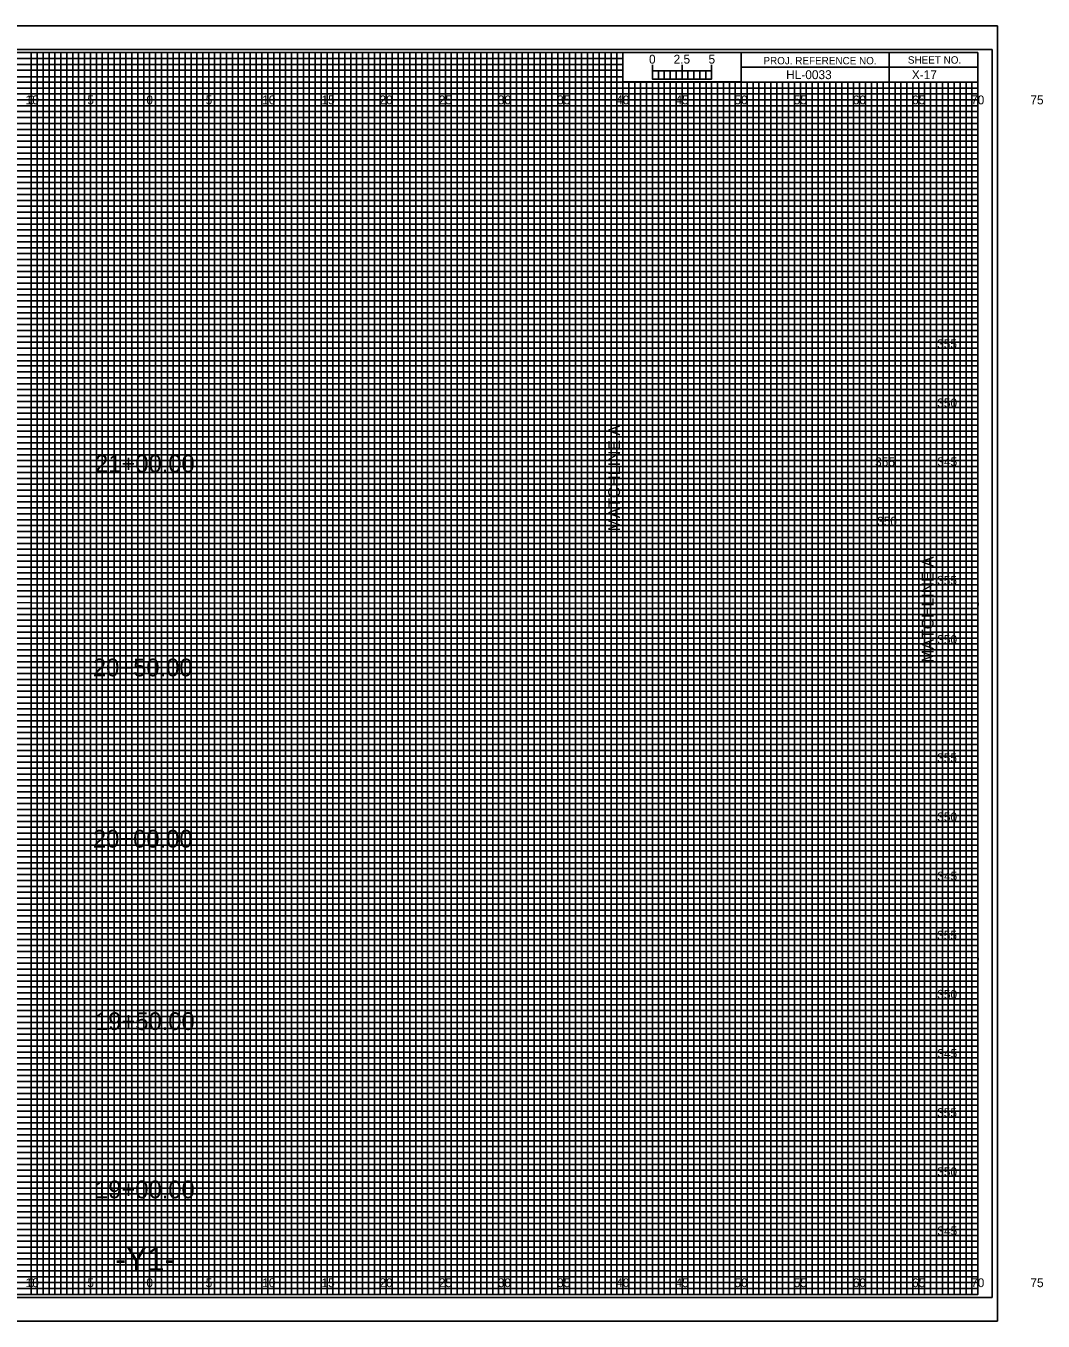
# Model space of a CAD drawing. Extents: x -7 to 166, y 218 to 327.
# Drawn here: x 79.5 to 165.5, y 217.7 to 327.2 of the extents above; entities that cross this region are included whole.
import ezdxf

# ---------------------------------------------------------------- set-up
doc = ezdxf.new("R2010")
doc.units = 0
for name, color, linetype in [('Prop XS Alignment Label', 7, 'Continuous'), ('Prop XS Bar Scale Labels', 7, 'Continuous'), ('Prop XS Elevation Labels', 7, 'Continuous'), ('Prop XS Hydro Elevations', 7, 'Continuous'), ('Prop XS Offset Labels', 7, 'Continuous'), ('Prop XS Project Number', 7, 'Continuous'), ('Prop XS Sheet Number', 7, 'Continuous'), ('Prop XS Station Labels', 7, 'Continuous'), ('Scratch_Level_0', 7, 'Continuous'), ('Sheet Cross Section CELL', 7, 'Continuous'), ('Sheet Cross Section Grid Major CELL', 7, 'Continuous'), ('Sheet Cross Section Grid Middle CELL', 7, 'Continuous'), ('Sheet Cross Section Grid Minor 1 CELL', 7, 'Continuous'), ('Sheet Cross Section Grid Minor 2 CELL', 7, 'Continuous'), ('Sheet Cross Section Scale CELL', 7, 'Continuous'), ('Sheet Cutting Line CELL', 7, 'Continuous'), ('Sheet DOT Grid CELL', 7, 'Continuous'), ('Sheet Plot Border Inside CELL', 7, 'Continuous'), ('Sheet Plot Border Outside CELL', 7, 'Continuous')]:
    doc.layers.add(name, color=color, linetype=linetype)

msp = doc.modelspace()

# ---------------------------------------------------------------- linework, layer by layer
at = {"layer": 'Prop XS Offset Labels'}
for p, q in [((130, 293.5), (130, 284)), ((155, 282.5), (155, 271.5))]:
    msp.add_line(p, q, dxfattribs=at)
msp.add_lwpolyline([(128, 294.5), (154.5, 294.5), (154.5, 283.5), (128, 283.5)], close=True, dxfattribs=at)
at = {"layer": 'Scratch_Level_0'}
msp.add_lwpolyline([(130, 293.5), (150, 293.5), (150, 284), (130, 284)], close=True, dxfattribs=at)
at = {"layer": 'Sheet Cross Section CELL'}
for p, q in [((152.5, 325), (152.5, 322.5)), ((152.5, 322.5), (152.5, 325)), ((160, 323.75), (140, 323.75)), ((140, 323.75), (140, 322.5)), ((140, 322.5), (160, 322.5))]:
    msp.add_line(p, q, dxfattribs=at)
for points in [[(160, 325), (0, 325), (0, 220), (160, 220)], [(140, 325), (130, 325), (130, 322.51), (140, 322.51)], [(160, 325), (140, 325), (140, 322.5), (160, 322.5)]]:
    msp.add_lwpolyline(points, close=True, dxfattribs=at)
at = {"layer": 'Sheet Cross Section Grid Major CELL'}
for p, q in [((85, 325), (80, 325)), ((80, 325), (80, 220)), ((85, 220), (85, 325)), ((95, 325), (90, 325)), ((90, 325), (90, 220)), ((95, 220), (95, 325)), ((105, 325), (100, 325)), ((100, 325), (100, 220)), ((105, 220), (105, 325)), ((115, 325), (110, 325)), ((110, 325), (110, 220)), ((115, 220), (115, 325)), ((125, 325), (120, 325)), ((120, 325), (120, 220)), ((125, 220), (125, 325)), ((130, 325), (130, 220)), ((135, 220), (135, 322.5)), ((145, 322.5), (140, 322.5)), ((140, 322.5), (140, 220)), ((145, 220), (145, 322.5)), ((155, 322.5), (150, 322.5)), ((150, 322.5), (150, 220)), ((155, 220), (155, 322.5)), ((80, 220), (75, 220)), ((90, 220), (85, 220)), ((100, 220), (95, 220)), ((110, 220), (105, 220)), ((120, 220), (115, 220)), ((130, 220), (125, 220)), ((140, 220), (135, 220)), ((150, 220), (145, 220)), ((160, 220), (155, 220)), ((160, 220), (160, 220))]:
    msp.add_line(p, q, dxfattribs=at)
for points in [[(0, 320), (160, 320), (160, 315), (0, 315)], [(0, 310), (160, 310), (160, 305), (0, 305)], [(0, 300), (160, 300), (160, 295), (0, 295)], [(0, 290), (160, 290), (160, 285), (0, 285)], [(0, 280), (160, 280), (160, 275), (0, 275)], [(0, 270), (160, 270), (160, 265), (0, 265)], [(0, 260), (160, 260), (160, 255), (0, 255)], [(0, 250), (160, 250), (160, 245), (0, 245)], [(0, 240), (160, 240), (160, 235), (0, 235)], [(0, 230), (160, 230), (160, 225), (0, 225)]]:
    msp.add_lwpolyline(points, dxfattribs=at)
at = {"layer": 'Sheet Cross Section Grid Middle CELL'}
for points in [[(77.5, 325), (82.5, 325), (82.5, 220), (87.5, 220), (87.5, 325), (92.5, 325), (92.5, 220), (97.5, 220), (97.5, 325), (102.5, 325), (102.5, 220), (107.5, 220), (107.5, 325), (112.5, 325), (112.5, 220), (117.5, 220), (117.5, 325), (122.5, 325), (122.5, 220), (127.5, 220), (127.5, 325), (129.97, 325), (130, 325), (130, 322.5), (132.5, 322.5), (132.5, 220), (137.5, 220), (137.5, 322.5), (142.5, 322.5), (142.5, 220), (147.5, 220), (147.5, 322.5), (152.5, 322.5), (152.5, 220), (157.5, 220), (157.5, 322.5)], [(0, 322.5), (137.5, 322.5)], [(0, 312.5), (160, 312.5), (160, 317.5), (0, 317.5)], [(0, 302.5), (160, 302.5), (160, 307.5), (0, 307.5)], [(0, 292.5), (160, 292.5), (160, 297.5), (0, 297.5)], [(0, 282.5), (160, 282.5), (160, 287.5), (0, 287.5)], [(0, 272.5), (160, 272.5), (160, 277.5), (0, 277.5)], [(0, 262.5), (160, 262.5), (160, 267.5), (0, 267.5)], [(0, 252.5), (160, 252.5), (160, 257.5), (0, 257.5)], [(0, 242.5), (160, 242.5), (160, 247.5), (0, 247.5)], [(0, 232.5), (160, 232.5), (160, 237.5), (0, 237.5)], [(0, 222.5), (160, 222.5), (160, 227.5), (0, 227.5)]]:
    msp.add_lwpolyline(points, dxfattribs=at)
at = {"layer": 'Sheet Cross Section Grid Minor 1 CELL'}
for p, q in [((0, 324.5), (130, 324.5)), ((130, 324.5), (130, 323.99)), ((130, 323.99), (0, 323.99)), ((0, 323.5), (130, 323.5)), ((130, 323.5), (130, 322.94)), ((130, 322.94), (0, 322.94)), ((0, 322), (160, 322))]:
    msp.add_line(p, q, dxfattribs=at)
for points in [[(0, 321.5), (135, 321.5), (160, 321.5), (160, 321), (0, 321)], [(0, 320.5), (160, 320.5), (160, 319.5), (0, 319.5)], [(0, 319), (160, 319), (160, 318.5), (0, 318.49)], [(0, 318), (160, 318), (160, 317), (0, 317)], [(0, 316.5), (160, 316.5), (160, 316), (0, 316)], [(0, 315.5), (160, 315.5), (160, 314.5), (0, 314.5)], [(0, 314), (160, 314), (160, 313.5), (0, 313.5)], [(0, 313), (160, 313), (160, 312), (0, 312)], [(0, 311.5), (160, 311.5), (160, 311), (0, 311)], [(0, 310.5), (160, 310.5), (160, 309.5), (0, 309.5)], [(0, 309), (160, 309), (160, 308.5), (0, 308.5)], [(0, 308), (160, 308), (160, 306.98), (160, 306.5), (160, 306), (0, 306)], [(0, 307), (160, 307), (160, 306.5), (0, 306.5)], [(0, 305.5), (160, 305.5), (160, 304.5), (0, 304.51)], [(0, 304.51), (160, 304.5), (160, 304), (0, 304)], [(0, 303.5), (160, 303.5), (160, 303), (0, 303)], [(0, 302), (160, 302), (160, 301.5), (0, 301.5)], [(0, 301), (160, 301), (160, 300.5), (0, 300.5)], [(-0.04, 299.44), (160, 299.44), (160, 298.94), (-0.04, 298.94)], [(0, 298.5), (160, 298.5), (160, 298), (0, 298)], [(0, 297), (160, 297), (160, 296.5), (0, 296.5)], [(0, 296), (160, 296), (160, 295.5), (0, 295.5)], [(0, 294.5), (160, 294.5), (160, 294), (0, 294)], [(0, 293.5), (160, 293.5), (160, 293), (0, 293)], [(0, 292), (160, 292), (160, 291.5), (0, 291.5)], [(0, 291), (160, 291), (160, 290.5), (0, 290.5)], [(0, 289.5), (160, 289.5), (160, 288.99), (0, 289)], [(0, 288.5), (160, 288.5), (160, 288), (0, 288)], [(0, 287), (160, 287), (160, 286.5), (0, 286.5)], [(0, 286), (160, 286), (160, 285.5), (0, 285.5)], [(0, 284.5), (160, 284.5), (160, 284), (0, 284)], [(0, 283.5), (160, 283.5), (160, 283), (0, 283)], [(0, 282), (160, 282), (160, 281.5), (0, 281.5)], [(0, 281), (160, 281), (160, 280.5), (0, 280.5)], [(0, 279.5), (160, 279.5), (160, 279), (0, 279)], [(0, 278.5), (160.03, 278.45), (160, 278), (0, 278)], [(0, 277), (160, 277), (160, 276.5), (0, 276.5)], [(0, 276), (160, 276), (160, 275.5), (0, 275.5)], [(0, 274.5), (160, 274.5), (160, 274), (0, 274)], [(0, 273.5), (160, 273.5), (160, 273), (0, 273)], [(0, 272), (160, 272), (160, 271.5), (0, 271.5)], [(0, 271), (160, 271), (160, 270.5), (0, 270.5)], [(0, 269.5), (160, 269.5), (160, 269), (0, 269)], [(0, 268.5), (160, 268.5), (160, 268), (0, 268)], [(0, 267), (160, 267), (160, 266.5), (0, 266.5)], [(0, 266), (160, 266), (160, 265.5), (0, 265.5)], [(0, 264.5), (160, 264.5), (160, 264), (0, 264)], [(0, 263.5), (160, 263.5), (160, 263), (0, 263)], [(0, 262), (160, 262), (160, 261.5), (0, 261.5)], [(0, 261), (160, 261), (160, 260.5), (0, 260.5)], [(0, 259.5), (160, 259.5), (160, 258.99), (0, 259)], [(0, 258.5), (160, 258.5), (160, 258), (0, 258)], [(0, 257), (160, 257), (160, 256.5), (0, 256.5)], [(0, 256), (160, 256), (160, 255.5), (0, 255.5)], [(0, 254.5), (160, 254.5), (160, 254), (0, 254)], [(0, 253.5), (160, 253.5), (160, 253), (0, 253)], [(0, 252), (160, 252), (160, 251.5), (0, 251.5)], [(0, 251), (160, 251), (160, 250.5), (0, 250.5)], [(0, 249.5), (160, 249.5), (160, 249), (0, 249)], [(0, 248.5), (160.03, 248.46), (160, 248), (0, 248)], [(0, 247), (160, 247), (160, 246.5), (0, 246.5)], [(0, 246), (160, 246), (160, 245.5), (0, 245.5)], [(0, 244.5), (160, 244.5), (160, 244), (0, 244)], [(0, 243.5), (160, 243.5), (160, 243), (0, 243)], [(0, 242), (160, 242), (160, 241.5), (0, 241.5)], [(0, 241), (160, 241), (160, 240.5), (0, 240.5)], [(0, 239.5), (160, 239.5), (160, 239), (0, 239)], [(0, 238.5), (160, 238.5), (160, 238), (0, 238)], [(0, 237), (160, 237), (160, 236.5), (0, 236.5)], [(0, 236), (160, 236), (160, 235.5), (0, 235.5)], [(0, 234.5), (160, 234.5), (160, 234), (0, 234)], [(0, 233.5), (160, 233.5), (160, 233), (0, 233)], [(0, 232), (160, 232), (160, 231.5), (0, 231.5)], [(0, 231), (160, 231), (160, 230.5), (0, 230.5)], [(0, 229.5), (160, 229.5), (160, 229), (0, 229)], [(0, 228.5), (160, 228.5), (160, 228), (0, 228)], [(0, 227), (160, 227), (160, 226.5), (0, 226.5)], [(0, 226), (160, 226), (160, 225.5), (0, 225.5)], [(0, 224.5), (160, 224.5), (160, 224), (0, 224)], [(0, 223.5), (160, 223.5), (160, 223), (0, 223)], [(0, 222), (160, 222), (160, 221.5), (0, 221.5)], [(0, 221), (160, 221), (160, 220.5), (0, 220.5)]]:
    msp.add_lwpolyline(points, dxfattribs=at)
at = {"layer": 'Sheet Cross Section Grid Minor 2 CELL'}
for p, q in [((133.5, 322.5), (133, 322.5)), ((133, 322.5), (133, 220)), ((133.5, 220), (133.5, 322.5)), ((134.5, 322.5), (134, 322.5)), ((134, 322.5), (134, 220)), ((134.5, 220), (134.5, 322.5)), ((133, 220), (132.5, 220)), ((134, 220), (133.5, 220))]:
    msp.add_line(p, q, dxfattribs=at)
for points in [[(80, 220), (80.5, 220), (80.5, 325), (81, 325), (81, 220)], [(81, 220), (81.5, 220), (81.5, 325), (82, 325), (82, 220)], [(82.5, 220), (83, 220), (83, 325), (83.5, 325), (83.5, 220)], [(83.5, 220), (84, 220), (84, 325), (84.5, 325), (84.5, 220)], [(85, 220), (85.5, 220), (85.5, 325), (86, 325), (86, 220)], [(86, 220), (86.5, 220), (86.5, 325), (87, 325), (87, 220)], [(87.5, 220), (88, 220), (88, 325), (88.5, 325), (88.5, 220)], [(88.5, 220), (89, 220), (89, 325), (89.5, 325), (89.5, 220)], [(90, 220), (90.5, 220), (90.5, 325), (91, 325), (91, 220)], [(91, 220), (91.5, 220), (91.5, 325), (92, 325), (92, 220)], [(92.5, 220), (93, 220), (93, 325), (93.5, 325), (93.5, 220)], [(93.5, 220), (94, 220), (94, 325), (94.5, 325), (94.5, 220)], [(95, 220), (95.5, 220), (95.5, 325), (96, 325), (96, 220)], [(96, 220), (96.5, 220), (96.5, 325), (97, 325), (97, 220)], [(97.5, 220), (98, 220), (98, 325), (98.5, 325), (98.5, 220)], [(98.5, 220), (99, 220), (99, 325), (99.5, 325), (99.5, 220)], [(100, 220), (100.5, 220), (100.5, 325), (101, 325), (101, 220)], [(101, 220), (101.5, 220), (101.5, 325), (102, 325), (102, 220)], [(102.5, 220), (103, 220), (103, 325), (103.5, 325), (103.5, 220)], [(103.5, 220), (104, 220), (104, 325), (104.5, 325), (104.5, 220)], [(105, 220), (105.5, 220), (105.5, 325), (106, 325), (106, 220)], [(106, 220), (106.5, 220), (106.5, 325), (107, 325), (107, 220)], [(107.5, 220), (108, 220), (108, 325), (108.5, 325), (108.5, 220)], [(108.5, 220), (109, 220), (109, 325), (109.5, 325), (109.5, 220)], [(110, 220), (110.5, 220), (110.5, 325), (111, 325), (111, 220)], [(111, 220), (111.5, 220), (111.5, 325), (112, 325), (112, 220)], [(112.5, 220), (113, 220), (113, 325), (113.5, 325), (113.5, 220)], [(113.5, 220), (114, 220), (114, 325), (114.5, 325), (114.5, 220)], [(115, 220), (115.5, 220), (115.5, 325), (116, 325), (116, 220)], [(116, 220), (116.5, 220), (116.5, 325), (117, 325), (117, 220)], [(117.5, 220), (118, 220), (118, 325), (118.5, 325), (118.5, 220)], [(118.5, 220), (119, 220), (119, 325), (119.5, 325), (119.5, 220)], [(120, 220), (120.5, 220), (120.5, 325), (121, 325), (121, 220)], [(121, 220), (121.5, 220), (121.5, 325), (122, 325), (122, 220)], [(122.5, 220), (123, 220), (123, 325), (123.5, 325), (123.5, 220)], [(123.5, 220), (124, 220), (124, 325), (124.5, 325), (124.5, 220)], [(125, 220), (125.5, 220), (125.5, 325), (126, 325), (126, 220)], [(126, 220), (126.5, 220), (126.5, 325), (127, 325), (127, 220)], [(127.5, 220), (128, 220), (128, 325), (128.5, 325), (128.5, 220)], [(128.5, 220), (129, 220), (129, 325), (129.5, 325), (129.5, 220)], [(130, 220), (130.5, 220), (130.5, 322.5), (131.01, 322.5), (131.01, 220)], [(131, 220), (131.5, 220), (131.5, 322.5), (132, 322.5), (132, 220)], [(135, 220), (135.49, 220), (135.49, 322.5), (136, 322.5), (136, 220)], [(136, 220), (136.5, 220), (136.5, 322.5), (137.03, 322.5), (137.03, 220)], [(137.5, 220), (138, 220), (138, 322.5), (138.5, 322.5), (138.5, 220)], [(138.5, 220), (139, 220), (139, 322.5), (139.5, 322.5), (139.5, 220)], [(140, 220), (140.5, 220), (140.5, 322.5), (141, 322.5), (141, 220)], [(141, 220), (141.5, 220), (141.5, 322.5), (142, 322.5), (142, 220)], [(142.5, 220), (143, 220), (143, 322.5), (143.5, 322.5), (143.5, 220)], [(143.5, 220), (144, 220), (144, 322.5), (144.5, 322.5), (144.5, 220)], [(145, 220), (145.5, 220), (145.5, 322.5), (146, 322.5), (146, 220)], [(146, 220), (146.5, 220), (146.5, 322.5), (147, 322.5), (147, 220)], [(147.5, 220), (148, 220), (148, 322.5), (148.5, 322.5), (148.5, 220)], [(148.5, 220), (149, 220), (149, 322.5), (149.5, 322.5), (149.5, 220)], [(150, 220), (150.5, 220), (150.5, 322.5), (151, 322.5), (151, 220)], [(151, 220), (151.5, 220), (151.5, 322.5), (152, 322.5), (152, 220)], [(152.5, 220), (153, 220), (153, 322.5), (153.5, 322.5), (153.5, 220)], [(153.5, 220), (154, 220), (154, 322.5), (154.5, 322.5), (154.5, 220)], [(155, 220), (155.5, 220), (155.5, 322.5), (156, 322.5), (156, 220)], [(156, 220), (156.5, 220), (156.5, 322.5), (157, 322.5), (157, 220)], [(157.5, 220), (158, 220), (158, 322.5), (158.5, 322.5), (158.5, 220)], [(158.5, 220), (159, 220), (159, 322.5), (159.5, 322.5), (159.5, 220)]]:
    msp.add_lwpolyline(points, dxfattribs=at)
at = {"layer": 'Sheet Cross Section Scale CELL'}
for p, q in [((132.5, 322.75), (132.5, 323.95)), ((132.5, 323.45), (132.5, 323.95)), ((135, 322.75), (135, 323.95)), ((137.5, 322.75), (137.5, 323.95)), ((137.5, 323.45), (137.5, 323.95))]:
    msp.add_line(p, q, dxfattribs=at)
for points in [[(137.5, 323.45), (132.5, 323.45), (132.5, 322.75), (137.5, 322.75)], [(132.5, 323.45), (133, 323.45), (133, 322.75), (132.5, 322.75)], [(133.5, 323.45), (134, 323.45), (134, 322.75), (133.5, 322.75)], [(134.5, 323.45), (135, 323.45), (135, 322.75), (134.5, 322.75)], [(135.5, 323.45), (136, 323.45), (136, 322.75), (135.5, 322.75)], [(136.5, 323.45), (137, 323.45), (137, 322.75), (136.5, 322.75)]]:
    msp.add_lwpolyline(points, close=True, dxfattribs=at)
at = {"layer": 'Sheet Cutting Line CELL'}
for p, q in [((161.65, 327.25), (-6.7, 327.25)), ((-6.7, 217.75), (161.65, 217.75))]:
    msp.add_line(p, q, dxfattribs=at)
at = {"layer": 'Sheet DOT Grid CELL'}
for p, q in [((80, 220), (80, 325)), ((85, 220), (85, 325)), ((90, 220), (90, 325)), ((95, 220), (95, 325)), ((100, 220), (100, 325)), ((105, 220), (105, 325)), ((110, 220), (110, 325)), ((115, 220), (115, 325)), ((120, 220), (120, 325)), ((125, 220), (125, 325)), ((130, 220), (130, 322.34)), ((135, 220), (135, 322.34)), ((140, 220), (140, 322.34)), ((145, 220), (145, 322.34)), ((150, 220), (150, 322.34)), ((155, 220), (155, 322.34)), ((0, 320), (160, 320)), ((0, 315), (160, 315)), ((0, 310), (160, 310)), ((0, 305), (160, 305)), ((0, 300), (160, 300)), ((0, 295), (160, 295)), ((0, 290), (160, 290)), ((0, 285), (160, 285)), ((0, 280), (160, 280)), ((0, 275), (160, 275)), ((0, 270), (160, 270)), ((0, 265), (160, 265)), ((0, 260), (160, 260)), ((0, 255), (160, 255)), ((0, 250), (160, 250)), ((0, 245), (160, 245)), ((0, 240), (160, 240)), ((0, 235), (160, 235)), ((0, 230), (160, 230)), ((0, 225), (160, 225))]:
    msp.add_line(p, q, dxfattribs=at)
at = {"layer": 'Sheet Plot Border Inside CELL'}
msp.add_lwpolyline([(-5.4, 219.75), (161.2, 219.75), (161.2, 325.25), (-5.4, 325.25)], close=True, dxfattribs=at)
at = {"layer": 'Sheet Plot Border Outside CELL'}
msp.add_lwpolyline([(-6.7, 217.75), (161.65, 217.75), (161.65, 327.25), (-6.7, 327.25)], close=True, dxfattribs=at)

# ---------------------------------------------------------------- texts
at = {"layer": 'Prop XS Alignment Label'}
msp.add_text('-Y1-', height=2, dxfattribs=at).set_placement((87.11, 222))
at = {"layer": 'Prop XS Bar Scale Labels'}
for s, p in [('2.5', (134.29, 324.06)), ('5', (137.24, 324.06))]:
    msp.add_text(s, height=0.75, dxfattribs=at).set_placement(p)
at = {"layer": 'Prop XS Elevation Labels'}
for s, p in [('355', (156.56, 300)), ('350', (156.57, 295)), ('355', (151.32, 290.02)), ('345', (156.58, 290.03)), ('350', (151.49, 285)), ('355', (156.56, 280)), ('350', (156.57, 275)), ('355', (156.56, 265)), ('350', (156.57, 260)), ('345', (156.58, 255)), ('355', (156.56, 250)), ('350', (156.57, 245)), ('345', (156.58, 240)), ('355', (156.56, 235)), ('350', (156.57, 230)), ('345', (156.58, 225))]:
    msp.add_text(s, height=0.75, dxfattribs=at).set_placement(p)
at = {"layer": 'Prop XS Hydro Elevations'}
for p in [(129.76, 284.51), (156.26, 273.41)]:
    msp.add_text('MATCHLINE A', height=1, rotation=90, dxfattribs=at).set_placement(p)
at = {"layer": 'Prop XS Offset Labels'}
for s, p in [('10', (79.52, 320.62)), ('0', (79.73, 320.62)), ('5', (84.74, 320.62)), ('0', (89.73, 320.62)), ('5', (94.74, 320.62)), ('10', (99.52, 320.62)), ('15', (104.53, 320.62)), ('20', (109.43, 320.62)), ('25', (114.44, 320.62)), ('30', (119.43, 320.62)), ('35', (124.44, 320.62)), ('40', (129.43, 320.62)), ('45', (134.44, 320.62)), ('50', (139.43, 320.62)), ('55', (144.44, 320.62)), ('60', (149.43, 320.62)), ('65', (154.44, 320.62)), ('70', (159.43, 320.62)), ('75', (164.44, 320.62)), ('10', (79.52, 220.62)), ('0', (79.73, 220.62)), ('5', (84.74, 220.62)), ('0', (89.73, 220.62)), ('5', (94.74, 220.62)), ('10', (99.52, 220.62)), ('15', (104.53, 220.62)), ('20', (109.43, 220.62)), ('25', (114.44, 220.62)), ('30', (119.43, 220.62)), ('35', (124.44, 220.62)), ('40', (129.43, 220.62)), ('45', (134.44, 220.62)), ('50', (139.43, 220.62)), ('55', (144.44, 220.62)), ('60', (149.43, 220.62)), ('65', (154.44, 220.62)), ('70', (159.43, 220.62)), ('75', (164.44, 220.62))]:
    msp.add_text(s, height=0.75, dxfattribs=at).set_placement(p)
at = {"layer": 'Prop XS Project Number'}
msp.add_text('HL-0033', height=0.75, dxfattribs=at).set_placement((143.8, 322.75))
at = {"layer": 'Prop XS Sheet Number'}
msp.add_text('X-17', height=0.75, dxfattribs=at).set_placement((154.42, 322.75))
at = {"layer": 'Prop XS Station Labels'}
for s, p in [('21+00.00', (85.39, 289.5)), ('20+50.00', (85.21, 272.26)), ('20+00.00', (85.21, 257.78)), ('19+50.00', (85.39, 242.36)), ('19+00.00', (85.39, 228.13))]:
    msp.add_text(s, height=1.5, dxfattribs=at).set_placement(p)
at = {"layer": 'Sheet Cross Section CELL'}
for s, p in [('PROJ. REFERENCE NO.', (141.88, 324)), ('SHEET NO.', (154.09, 324.06))]:
    msp.add_text(s, height=0.625, dxfattribs=at).set_placement(p)
at = {"layer": 'Sheet Cross Section Scale CELL'}
msp.add_text('0', height=0.75, dxfattribs=at).set_placement((132.21, 324.06))

doc.saveas('drawing.dxf')
